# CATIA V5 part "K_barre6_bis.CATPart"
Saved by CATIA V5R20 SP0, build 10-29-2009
Part number: barre_6_bis
Bounding box of the stored display mesh (mm): x -43.04 to 2.493, y -2 to 1, z 34.495 to 58.999
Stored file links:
  G:\Khaled_CFAO_2011\ST2M\ST2M_GR2\gcausse\Khaled\CAD_ThinkMotion\K_barre6_bis.CATPart
  C:\Documents and Settings\gcausse\Bureau\video thinkmotio\assemblage_gcausse\pupitre_think.CATProduct
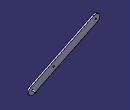
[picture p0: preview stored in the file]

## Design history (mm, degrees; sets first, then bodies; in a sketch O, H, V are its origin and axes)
Set1
  Sketch1 on Plane1, origin (0, -1, 0), H (-1, 0, 0), V (0, 0, 1)
    line L1 (39.4627, 58.7585) -> (-1.0843, 39.2408)
    arc A1 centre (0, 36.9882) radius 2.5 from (-1.0843, 39.2408) to (1.0843, 34.7356) ccw
    point P3 (0, 36.9882)
    line L2 (1.0843, 34.7356) -> (41.6313, 54.2533)
    arc A2 centre (40.547, 56.5059) radius 2.5 from (41.6313, 54.2533) to (39.4627, 58.7585) ccw
    point P6 (40.547, 56.5059)
    reference projected point E1 (40.547, 56.5059) from Point1
    reference projected line E2 (40.547, 56.5059) -> (0, 36.9882) from Line1
    reference projected line E3 (40.547, 56.5059) -> (0, 36.9882) from Line1
    reference projected point E4 (0, 36.9882) from Point2
    distance L1 L2 = 5
    tangency: A1 L1, L2 A1, A2 L1, A2 L2
    coincidence: P6 E1, P3 E4
    parallelism: L1 E2, L2 E3
Set2
  Plane1: linked copy from another document
  Point1: linked copy from another document
  Line1: linked copy from another document
  Point2: linked copy from another document
  Point3: linked copy from another document
Set3
  Point4: type Center, Curve edge [face of Pad2 from Sketch4.A1 | end face of Pad2]
Body1 (main body)
  Pad1: profile Sketch1, direction (0, 1, 0), length -1
  Sketch2 on start face of Pad1, origin (-16.0921, -1, 45.6595), H (1, 0, 0), V (0, 0, -1)
    point P1 (2.5765, 2.1654)
    reference projected point E1 (2.5765, 2.1654) from Point3
    coincidence: P1 E1
  Hole1: placed by Sketch2, at (-13.5157, -1, 43.4941) direction (0, -1, 0), diameter 1, depth 1
  Sketch3 on start face of Pad1, origin (-42.0053, -1, 56.4382), H (1, 0, 0), V (0, 0, -1)
    point P1 (1.4583, -0.0677)
    reference projected point E1 (1.4583, -0.0677) from Point1
    coincidence: P1 E1
  Hole2: placed by Sketch3, at (-40.547, -1, 56.5059) direction (0, -1, 0), diameter 1, depth 1
  Sketch4 on start face of Pad1, origin (0, -1, 0), H (-1, 0, 0), V (0, 0, 1)
    circle A1 centre (0, 36.9882) radius 0.5
    point P1 (0, 36.9882)
    reference projected point E1 (0, 36.9882) from Point2
    coincidence: P1 E1
  Pad2: profile Sketch4, direction (0, 1, 0), length 2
